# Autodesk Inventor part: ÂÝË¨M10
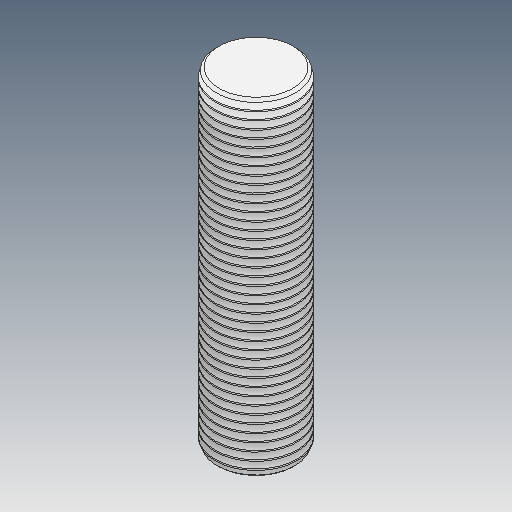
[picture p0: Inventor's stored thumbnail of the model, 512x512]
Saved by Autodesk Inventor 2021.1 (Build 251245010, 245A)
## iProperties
Created: 2021-05
Part Number: ÂÝË¨M10
Material: Ogólny
Document SubType Name: Modeling
Designer: user
Density: 1 g/cm^3
Appearance: Domyślna
Author: user
Revision Number: ÈÎºÎ
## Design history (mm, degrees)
feature "ÊäÈë1"
node "Bryła1"
